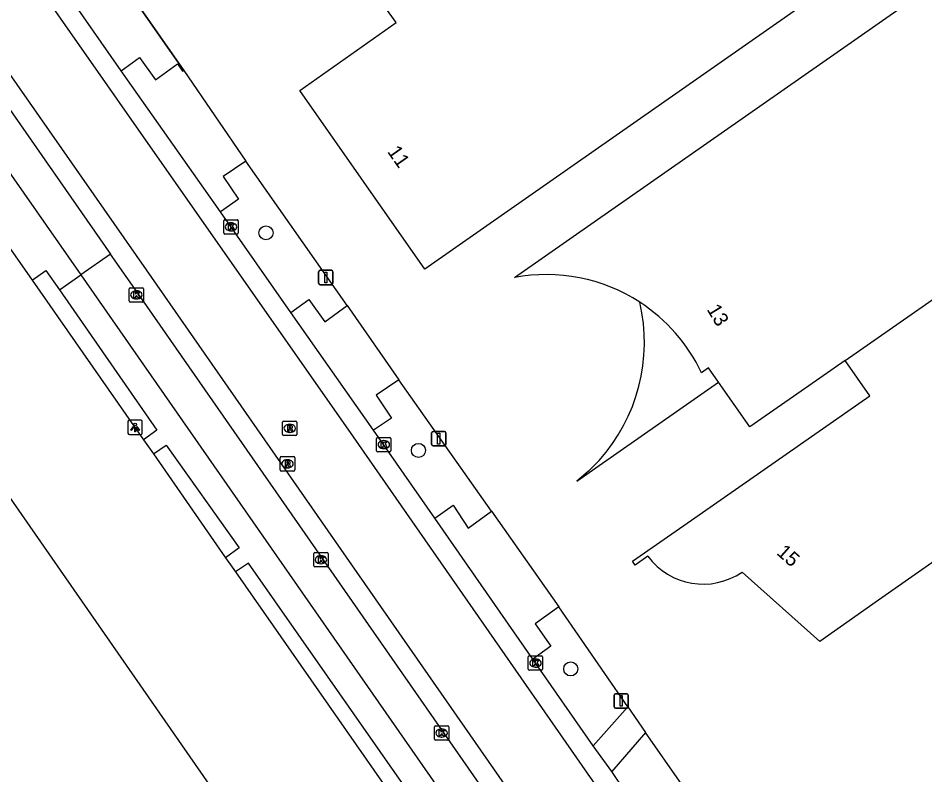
# Model space of a CAD drawing. Extents: x 156651 to 158072, y 387631 to 388990.
# Drawn here: x 157227.4 to 157290.6, y 388154.9 to 388207.5 of the extents above; entities that cross this region are included whole.
import ezdxf

# ---------------------------------------------------------------- set-up
doc = ezdxf.new("R2010")
doc.units = 0
for name, color, linetype in [('IMGEO_Berm_groen', 7, 'Continuous'), ('IMGEO_Boom', 7, 'Continuous'), ('IMGEO_Groenvoorziening', 7, 'Continuous'), ('IMGEO_Hek', 7, 'Continuous'), ('IMGEO_Kolk', 7, 'Continuous'), ('IMGEO_Lichtpunt', 7, 'Continuous'), ('IMGEO_Pand', 7, 'Continuous'), ('IMGEO_Pand_nummerreeks', 7, 'Continuous'), ('IMGEO_Pand_overbouw', 7, 'Continuous'), ('IMGEO_Rijbaan_lokaal_gesloten', 7, 'Continuous'), ('IMGEO_Rijbaan_lokaal_open', 7, 'Continuous'), ('IMGEO_Rioolput', 7, 'Continuous'), ('IMGEO_Verkeersbordpaal', 7, 'Continuous'), ('IMGEO_Voetpad_open', 7, 'Continuous')]:
    doc.layers.add(name, color=color, linetype=linetype)

msp = doc.modelspace()

# ---------------------------------------------------------------- linework, layer by layer
at = {"layer": 'IMGEO_Berm_groen'}
for points in [[(157238.976, 388203.904), (157232.439, 388213.235)], [(157250.344, 388187.533), (157243.285, 388197.598)], [(157260.401, 388173.229), (157253.951, 388182.374)], [(157269.88, 388159.622), (157265.086, 388166.567)], [(157273.661, 388154.215), (157271.116, 388157.832)]]:
    msp.add_lwpolyline(points, dxfattribs=at)
at = {"layer": 'IMGEO_Boom'}
for centre in [(157244.691, 388192.6), (157255.309, 388177.463), (157265.912, 388162.252)]:
    msp.add_circle(centre, 0.489, dxfattribs=at)
at = {"layer": 'IMGEO_Groenvoorziening'}
for points in [[(157228.416, 388189.316), (157236.169, 388178.201)], [(157236.847, 388177.226), (157241.87, 388169.99)], [(157242.574, 388169.007), (157265.86, 388135.653), (157271.06, 388128.215)]]:
    msp.add_lwpolyline(points, dxfattribs=at)
at = {"layer": 'IMGEO_Hek'}
msp.add_lwpolyline([(157232.439, 388213.235), (157238.976, 388203.904)], dxfattribs=at)
at = {"layer": 'IMGEO_Kolk'}
for p, q in [((157241.755, 388192.591), (157241.755, 388193.443)), ((157241.83, 388193.517), (157242.682, 388193.517)), ((157242.243, 388193.297), (157242.268, 388193.297)), ((157242.756, 388193.443), (157242.756, 388192.591)), ((157242.682, 388192.517), (157241.83, 388192.517)), ((157242.266, 388192.737), (157242.241, 388192.737)), ((157235.165, 388187.858), (157235.165, 388188.71)), ((157235.24, 388188.784), (157236.092, 388188.784)), ((157235.653, 388188.564), (157235.678, 388188.564)), ((157236.166, 388188.71), (157236.166, 388187.858)), ((157235.676, 388188.004), (157235.651, 388188.004)), ((157236.092, 388187.784), (157235.24, 388187.784)), ((157252.393, 388177.436), (157252.393, 388178.288)), ((157252.468, 388178.362), (157253.32, 388178.362)), ((157252.881, 388178.142), (157252.906, 388178.142)), ((157253.394, 388178.288), (157253.394, 388177.436)), ((157253.32, 388177.362), (157252.468, 388177.362)), ((157252.904, 388177.582), (157252.879, 388177.582)), ((157248.018, 388169.428), (157248.018, 388170.28)), ((157248.093, 388170.354), (157248.945, 388170.354)), ((157249.019, 388170.28), (157249.019, 388169.428)), ((157248.529, 388169.574), (157248.504, 388169.574)), ((157248.506, 388170.134), (157248.531, 388170.134)), ((157248.945, 388169.354), (157248.093, 388169.354)), ((157262.957, 388162.232), (157262.957, 388163.084)), ((157263.032, 388163.158), (157263.884, 388163.158)), ((157263.445, 388162.938), (157263.47, 388162.938)), ((157263.958, 388163.084), (157263.958, 388162.232)), ((157263.884, 388162.158), (157263.032, 388162.158)), ((157263.468, 388162.378), (157263.443, 388162.378)), ((157256.423, 388157.369), (157256.423, 388158.221)), ((157256.498, 388158.295), (157257.35, 388158.295)), ((157257.424, 388158.221), (157257.424, 388157.369)), ((157256.911, 388158.075), (157256.936, 388158.075)), ((157257.35, 388157.295), (157256.498, 388157.295)), ((157256.934, 388157.515), (157256.909, 388157.515))]:
    msp.add_line(p, q, dxfattribs=at)
for points in [[(157241.755, 388192.591), (157241.755, 388193.443)], [(157241.83, 388193.517), (157242.682, 388193.517)], [(157242.076, 388193.217), (157242.199, 388193.217), (157242.199, 388193.066), (157242.329, 388193.217), (157242.493, 388193.217), (157242.347, 388193.066), (157242.5, 388192.817), (157242.348, 388192.817), (157242.263, 388192.981), (157242.199, 388192.914), (157242.199, 388192.817), (157242.076, 388192.817), (157242.076, 388193.217)], [(157242.756, 388193.443), (157242.756, 388192.591)], [(157242.682, 388192.517), (157241.83, 388192.517)], [(157235.165, 388187.858), (157235.165, 388188.71)], [(157235.24, 388188.784), (157236.092, 388188.784)], [(157235.486, 388188.484), (157235.609, 388188.484), (157235.609, 388188.333), (157235.739, 388188.484), (157235.903, 388188.484), (157235.757, 388188.333), (157235.91, 388188.084), (157235.758, 388188.084), (157235.673, 388188.248), (157235.609, 388188.181), (157235.609, 388188.084), (157235.486, 388188.084), (157235.486, 388188.484)], [(157236.166, 388188.71), (157236.166, 388187.858)], [(157236.092, 388187.784), (157235.24, 388187.784)], [(157252.393, 388177.436), (157252.393, 388178.288)], [(157252.468, 388178.362), (157253.32, 388178.362)], [(157252.714, 388178.062), (157252.837, 388178.062), (157252.837, 388177.911), (157252.967, 388178.062), (157253.131, 388178.062), (157252.985, 388177.911), (157253.138, 388177.662), (157252.986, 388177.662), (157252.901, 388177.826), (157252.837, 388177.759), (157252.837, 388177.662), (157252.714, 388177.662), (157252.714, 388178.062)], [(157253.394, 388178.288), (157253.394, 388177.436)], [(157253.32, 388177.362), (157252.468, 388177.362)], [(157248.018, 388169.428), (157248.018, 388170.28)], [(157248.093, 388170.354), (157248.945, 388170.354)], [(157249.019, 388170.28), (157249.019, 388169.428)], [(157248.339, 388170.054), (157248.462, 388170.054), (157248.462, 388169.903), (157248.592, 388170.054), (157248.756, 388170.054), (157248.61, 388169.903), (157248.763, 388169.654), (157248.611, 388169.654), (157248.526, 388169.818), (157248.462, 388169.751), (157248.462, 388169.654), (157248.339, 388169.654), (157248.339, 388170.054)], [(157248.945, 388169.354), (157248.093, 388169.354)], [(157262.957, 388162.232), (157262.957, 388163.084)], [(157263.032, 388163.158), (157263.884, 388163.158)], [(157263.278, 388162.858), (157263.401, 388162.858), (157263.401, 388162.707), (157263.531, 388162.858), (157263.695, 388162.858), (157263.549, 388162.707), (157263.702, 388162.458), (157263.55, 388162.458), (157263.465, 388162.622), (157263.401, 388162.555), (157263.401, 388162.458), (157263.278, 388162.458), (157263.278, 388162.858)], [(157263.958, 388163.084), (157263.958, 388162.232)], [(157263.884, 388162.158), (157263.032, 388162.158)], [(157256.423, 388157.369), (157256.423, 388158.221)], [(157256.498, 388158.295), (157257.35, 388158.295)], [(157257.424, 388158.221), (157257.424, 388157.369)], [(157256.744, 388157.995), (157256.867, 388157.995), (157256.867, 388157.844), (157256.997, 388157.995), (157257.161, 388157.995), (157257.015, 388157.844), (157257.168, 388157.595), (157257.016, 388157.595), (157256.931, 388157.759), (157256.867, 388157.692), (157256.867, 388157.595), (157256.744, 388157.595), (157256.744, 388157.995)], [(157257.35, 388157.295), (157256.498, 388157.295)]]:
    msp.add_lwpolyline(points, dxfattribs=at)
for centre, start, end in [((157241.832, 388193.441), 91.55205, 178.44795), ((157241.832, 388193.441), 91.55205, 178.44795), ((157242.68, 388193.441), 1.55205, 88.44795), ((157242.68, 388193.441), 1.55205, 88.44795), ((157241.832, 388192.593), 181.55205, 268.44795), ((157241.832, 388192.593), 181.55205, 268.44795), ((157242.68, 388192.593), 271.55205, 358.44795), ((157242.68, 388192.593), 271.55205, 358.44795), ((157235.242, 388188.708), 91.55205, 178.44795), ((157235.242, 388188.708), 91.55205, 178.44795), ((157236.09, 388188.708), 1.55205, 88.44795), ((157236.09, 388188.708), 1.55205, 88.44795), ((157235.242, 388187.86), 181.55205, 268.44795), ((157235.242, 388187.86), 181.55205, 268.44795), ((157236.09, 388187.86), 271.55205, 358.44795), ((157236.09, 388187.86), 271.55205, 358.44795), ((157252.47, 388178.286), 91.55205, 178.44795), ((157252.47, 388178.286), 91.55205, 178.44795), ((157253.318, 388178.286), 1.55205, 88.44795), ((157253.318, 388178.286), 1.55205, 88.44795), ((157252.47, 388177.438), 181.55205, 268.44795), ((157252.47, 388177.438), 181.55205, 268.44795), ((157253.318, 388177.438), 271.55205, 358.44795), ((157253.318, 388177.438), 271.55205, 358.44795), ((157248.095, 388170.278), 91.55205, 178.44795), ((157248.095, 388170.278), 91.55205, 178.44795), ((157248.943, 388170.278), 1.55205, 88.44795), ((157248.943, 388170.278), 1.55205, 88.44795), ((157248.095, 388169.43), 181.55205, 268.44795), ((157248.095, 388169.43), 181.55205, 268.44795), ((157248.943, 388169.43), 271.55205, 358.44795), ((157248.943, 388169.43), 271.55205, 358.44795), ((157263.034, 388163.082), 91.55205, 178.44795), ((157263.034, 388163.082), 91.55205, 178.44795), ((157263.882, 388163.082), 1.55205, 88.44795), ((157263.882, 388163.082), 1.55205, 88.44795), ((157263.034, 388162.234), 181.55205, 268.44795), ((157263.034, 388162.234), 181.55205, 268.44795), ((157263.882, 388162.234), 271.55205, 358.44795), ((157263.882, 388162.234), 271.55205, 358.44795), ((157256.5, 388158.219), 91.55205, 178.44795), ((157256.5, 388158.219), 91.55205, 178.44795), ((157257.348, 388158.219), 1.55205, 88.44795), ((157257.348, 388158.219), 1.55205, 88.44795), ((157256.5, 388157.371), 181.55205, 268.44795), ((157256.5, 388157.371), 181.55205, 268.44795), ((157257.348, 388157.371), 271.55205, 358.44795), ((157257.348, 388157.371), 271.55205, 358.44795)]:
    msp.add_arc(centre, 0.0765, start, end, dxfattribs=at)
for centre, major_axis, ratio, start_param, end_param in [((157242.242, 388193.017), (-0.387, 0.002), 0.722429, 4.712389, 7.853982), ((157242.267, 388193.017), (-0.39, 0.002), 0.717154, 1.570796, 4.712389), ((157235.652, 388188.284), (-0.387, 0.002), 0.722429, 4.712389, 7.853982), ((157235.677, 388188.284), (-0.39, 0.002), 0.717154, 1.570796, 4.712389), ((157252.88, 388177.862), (-0.387, 0.002), 0.722429, 4.712389, 7.853982), ((157252.905, 388177.862), (-0.39, 0.002), 0.717154, 1.570796, 4.712389), ((157248.505, 388169.854), (-0.387, 0.002), 0.722429, 4.712389, 7.853982), ((157248.53, 388169.854), (-0.39, 0.002), 0.717154, 1.570796, 4.712389), ((157263.444, 388162.658), (-0.387, 0.002), 0.722429, 4.712389, 7.853982), ((157263.469, 388162.658), (-0.39, 0.002), 0.717154, 1.570796, 4.712389), ((157256.91, 388157.795), (-0.387, 0.002), 0.722429, 4.712389, 7.853982), ((157256.935, 388157.795), (-0.39, 0.002), 0.717154, 1.570796, 4.712389)]:
    msp.add_ellipse(centre, major_axis=major_axis, ratio=ratio, start_param=start_param, end_param=end_param, dxfattribs=at)
at = {"layer": 'IMGEO_Lichtpunt'}
for p, q in [((157235.081, 388179.468), (157235.081, 388178.661)), ((157235.081, 388179.468), (157235.081, 388178.661)), ((157235.983, 388179.563), (157235.175, 388179.563)), ((157235.983, 388179.563), (157235.175, 388179.563)), ((157236.077, 388178.661), (157236.077, 388179.468)), ((157236.077, 388178.661), (157236.077, 388179.468)), ((157235.175, 388178.567), (157235.983, 388178.567)), ((157235.175, 388178.567), (157235.983, 388178.567))]:
    msp.add_line(p, q, dxfattribs=at)
for points in [[(157235.455, 388179.132), (157235.494, 388179.104), (157235.306, 388178.842), (157235.268, 388178.869), (157235.455, 388179.132)], [(157235.557, 388179.084), (157235.604, 388179.084), (157235.604, 388178.762), (157235.557, 388178.762), (157235.557, 388179.084)], [(157235.667, 388179.104), (157235.705, 388179.131), (157235.892, 388178.869), (157235.853, 388178.841), (157235.667, 388179.104)]]:
    msp.add_lwpolyline(points, dxfattribs=at)
msp.add_circle((157235.58, 388179.266), 0.0994, dxfattribs=at)
for centre, start, end in [((157235.175, 388179.468), 90, 180), ((157235.175, 388179.468), 90, 180), ((157235.983, 388179.468), 0, 90), ((157235.983, 388179.468), 0, 90), ((157235.175, 388178.661), 180, 270), ((157235.175, 388178.661), 180, 270), ((157235.983, 388178.661), 270, 0), ((157235.983, 388178.661), 270, 360)]:
    msp.add_arc(centre, 0.0946, start, end, dxfattribs=at)
at = {"layer": 'IMGEO_Pand'}
for points in [[(157288.942, 388238.83), (157300.956, 388221.652), (157259.851, 388192.936), (157255.752, 388190.072), (157247.043, 388202.516), (157253.751, 388207.231), (157250.416, 388211.885), (157254.514, 388214.751), (157273.145, 388227.807)], [(157261.992, 388189.493), (157266.09, 388192.357), (157305.779, 388220.064), (157307.103, 388218.166), (157309.496, 388219.835), (157317.678, 388208.106), (157315.286, 388206.437), (157316.061, 388205.325), (157295.222, 388190.815)], [(157295.222, 388190.815), (157296.945, 388188.34), (157306.793, 388195.191), (157315.806, 388182.235), (157299.201, 388170.684), (157297.021, 388173.804), (157287.352, 388167.038), (157283.255, 388164.171), (157277.844, 388168.992)], [(157285.036, 388183.723), (157295.222, 388190.815)], [(157271.289, 388170.091), (157270.399, 388169.476), (157270.213, 388169.744), (157274.318, 388172.6), (157286.756, 388181.252), (157285.036, 388183.723)], [(157285.036, 388183.723), (157282.491, 388181.951), (157278.39, 388179.09), (157276.216, 388182.206), (157275.518, 388183.206), (157275.025, 388182.861)], [(157257.578, 388129.897), (157248.5, 388123.588), (157239.125, 388137.125), (157237.62, 388139.301), (157246.706, 388145.644), (157221.693, 388181.584), (157212.642, 388175.281), (157211.076, 388177.53), (157208.169, 388175.506), (157161.84, 388143.245), (157189.962, 388102.891), (157199.722, 388088.956), (157214.226, 388068.097), (157272.425, 388108.581), (157257.578, 388129.897)]]:
    msp.add_lwpolyline(points, dxfattribs=at)
for centre, radius, start, end in [((157264.215, 388177.734), 11.967, 57.02063, 100.70526), ((157264.213, 388177.74), 11.964, 25.34614, 56.99928), ((157275.137, 388172.942), 4.789, 216.53451, 304.43031)]:
    msp.add_arc(centre, radius, start, end, dxfattribs=at)
at = {"layer": 'IMGEO_Pand_overbouw'}
msp.add_lwpolyline([(157267.89, 388176.764), (157267.153, 388176.012), (157266.338, 388175.314), (157267.905, 388176.407), (157276.216, 388182.206), (157275.518, 388183.206), (157275.025, 388182.861)], dxfattribs=at)
for centre, radius, start, end in [((157258.767, 388184.987), 12.282, 317.96841, 13.11083), ((157264.213, 388177.74), 11.964, 25.34614, 56.99928)]:
    msp.add_arc(centre, radius, start, end, dxfattribs=at)
at = {"layer": 'IMGEO_Rijbaan_lokaal_gesloten'}
for points in [[(157341.899, 388076.038), (157340.456, 388076.982), (157309.901, 388101.717), (157302.391, 388108.413), (157297.417, 388113.326), (157292.839, 388118.359), (157292.715, 388118.524), (157290.068, 388122.059), (157284.128, 388130.537), (157250.785, 388178.4), (157218.017, 388225.194), (157168.536, 388296.106), (157166.328, 388299.54), (157165.346, 388302.72), (157165.232, 388304.849), (157165.572, 388307.171), (157166.44, 388309.461), (157166.862, 388310.136)], [(157159.256, 388297.816), (157160.307, 388298.772), (157166.301, 388290.299), (157236.347, 388190.018), (157288.771, 388114.767), (157287.657, 388113.917)], [(157234.617, 388203.884), (157230.6, 388209.644)], [(157241.532, 388194.055), (157234.617, 388203.884)], [(157225.926, 388202.493), (157233.871, 388191.118)], [(157246.429, 388187.061), (157241.532, 388194.055)], [(157274.579, 388132.691), (157236.036, 388188.018), (157233.871, 388191.118)], [(157252.169, 388178.864), (157246.429, 388187.061)], [(157256.455, 388172.746), (157252.169, 388178.864)], [(157263.265, 388162.929), (157256.455, 388172.746)], [(157267.467, 388156.891), (157263.265, 388162.929)], [(157268.767, 388155.125), (157267.467, 388156.891)], [(157269.683, 388153.769), (157268.767, 388155.125)]]:
    msp.add_lwpolyline(points, dxfattribs=at)
at = {"layer": 'IMGEO_Rijbaan_lokaal_open'}
for points in [[(157234.617, 388203.884), (157235.884, 388204.792), (157236.993, 388203.247), (157238.529, 388204.367), (157238.878, 388203.847), (157238.976, 388203.904)], [(157238.976, 388203.904), (157243.285, 388197.598)], [(157243.285, 388197.598), (157241.71, 388196.51), (157242.786, 388194.938), (157241.532, 388194.055)], [(157246.429, 388187.061), (157247.671, 388187.969), (157248.791, 388186.418), (157250.344, 388187.533)], [(157250.344, 388187.533), (157253.951, 388182.374)], [(157253.951, 388182.374), (157252.369, 388181.296), (157253.443, 388179.711), (157252.169, 388178.864)], [(157256.455, 388172.746), (157257.73, 388173.658), (157258.77, 388172.059), (157260.401, 388173.229)], [(157260.401, 388173.229), (157265.086, 388166.567)], [(157265.086, 388166.567), (157263.445, 388165.387), (157264.54, 388163.836), (157263.265, 388162.929)]]:
    msp.add_lwpolyline(points, dxfattribs=at)
at = {"layer": 'IMGEO_Rioolput'}
for p, q in [((157245.845, 388178.571), (157245.845, 388179.423)), ((157245.92, 388179.497), (157246.772, 388179.497)), ((157246.333, 388179.277), (157246.358, 388179.277)), ((157246.846, 388179.423), (157246.846, 388178.571)), ((157246.772, 388178.497), (157245.92, 388178.497)), ((157246.356, 388178.717), (157246.331, 388178.717)), ((157245.689, 388176.101), (157245.689, 388176.953)), ((157245.764, 388177.027), (157246.616, 388177.027)), ((157246.177, 388176.807), (157246.202, 388176.807)), ((157246.69, 388176.953), (157246.69, 388176.101)), ((157246.616, 388176.027), (157245.764, 388176.027)), ((157246.2, 388176.247), (157246.175, 388176.247))]:
    msp.add_line(p, q, dxfattribs=at)
for points in [[(157245.845, 388178.571), (157245.845, 388179.423)], [(157245.92, 388179.497), (157246.772, 388179.497)], [(157246.434, 388179.195), (157246.182, 388179.197), (157246.182, 388178.797)], [(157246.36, 388179.116), (157246.306, 388179.116), (157246.306, 388179.035)], [(157246.306, 388179.035), (157246.358, 388179.035)], [(157246.846, 388179.423), (157246.846, 388178.571)], [(157246.772, 388178.497), (157245.92, 388178.497)], [(157246.182, 388178.797), (157246.306, 388178.797), (157246.306, 388178.959), (157246.317, 388178.959)], [(157246.364, 388178.93), (157246.435, 388178.797), (157246.575, 388178.797), (157246.51, 388178.923)], [(157245.689, 388176.101), (157245.689, 388176.953)], [(157245.764, 388177.027), (157246.616, 388177.027)], [(157246.278, 388176.725), (157246.026, 388176.727), (157246.026, 388176.327)], [(157246.026, 388176.327), (157246.15, 388176.327), (157246.15, 388176.489), (157246.161, 388176.489)], [(157246.204, 388176.646), (157246.15, 388176.646), (157246.15, 388176.565)], [(157246.15, 388176.565), (157246.202, 388176.565)], [(157246.69, 388176.953), (157246.69, 388176.101)], [(157246.616, 388176.027), (157245.764, 388176.027)], [(157246.208, 388176.46), (157246.279, 388176.327), (157246.419, 388176.327), (157246.354, 388176.453)]]:
    msp.add_lwpolyline(points, dxfattribs=at)
for centre, radius, start, end in [((157245.922, 388179.421), 0.0765, 91.55205, 178.44795), ((157245.922, 388179.421), 0.0765, 91.55205, 178.44795), ((157246.342, 388179.224), 0.19, 274.7715, 282.96867), ((157246.366, 388179.02), 0.0964, 77.00612, 93.18647), ((157246.38, 388179.077), 0.0378, 276.66336, 79.67722), ((157246.433, 388179.085), 0.109, 350.36119, 89.41601), ((157246.431, 388179.085), 0.112, 277.58423, 350.98172), ((157246.77, 388179.421), 0.0765, 1.55205, 88.44795), ((157246.77, 388179.421), 0.0765, 1.55205, 88.44795), ((157245.922, 388178.573), 0.0765, 181.55205, 268.44795), ((157245.922, 388178.573), 0.0765, 181.55205, 268.44795), ((157246.316, 388178.906), 0.0533, 26.02933, 88.69889), ((157246.415, 388178.87), 0.108, 29.51342, 73.79051), ((157246.77, 388178.573), 0.0765, 271.55205, 358.44795), ((157246.77, 388178.573), 0.0765, 271.55205, 358.44795), ((157245.766, 388176.951), 0.0765, 91.55205, 178.44795), ((157245.766, 388176.951), 0.0765, 91.55205, 178.44795), ((157246.16, 388176.436), 0.0533, 26.02933, 88.69889), ((157246.186, 388176.754), 0.19, 274.7715, 282.96867), ((157246.21, 388176.55), 0.0964, 77.00612, 93.18647), ((157246.224, 388176.607), 0.0378, 276.66336, 79.67722), ((157246.277, 388176.615), 0.109, 350.36119, 89.41601), ((157246.275, 388176.615), 0.112, 277.58423, 350.98172), ((157246.259, 388176.4), 0.108, 29.51342, 73.79051), ((157246.614, 388176.951), 0.0765, 1.55205, 88.44795), ((157246.614, 388176.951), 0.0765, 1.55205, 88.44795), ((157245.766, 388176.103), 0.0765, 181.55205, 268.44795), ((157245.766, 388176.103), 0.0765, 181.55205, 268.44795), ((157246.614, 388176.103), 0.0765, 271.55205, 358.44795), ((157246.614, 388176.103), 0.0765, 271.55205, 358.44795)]:
    msp.add_arc(centre, radius, start, end, dxfattribs=at)
for centre, major_axis, ratio, start_param, end_param in [((157246.332, 388178.997), (-0.387, 0.002), 0.722429, 4.712389, 7.853982), ((157246.357, 388178.997), (-0.39, 0.002), 0.717154, 1.570796, 4.712389), ((157246.176, 388176.527), (-0.387, 0.002), 0.722429, 4.712389, 7.853982), ((157246.201, 388176.527), (-0.39, 0.002), 0.717154, 1.570796, 4.712389)]:
    msp.add_ellipse(centre, major_axis=major_axis, ratio=ratio, start_param=start_param, end_param=end_param, dxfattribs=at)
at = {"layer": 'IMGEO_Verkeersbordpaal'}
for p, q in [((157248.359, 388189.093), (157248.359, 388189.893)), ((157248.359, 388189.893), (157248.359, 388189.093)), ((157248.459, 388189.993), (157249.249, 388189.993)), ((157249.249, 388189.993), (157248.459, 388189.993)), ((157249.349, 388189.893), (157249.349, 388189.093)), ((157249.349, 388189.093), (157249.349, 388189.893)), ((157249.249, 388188.993), (157248.459, 388188.993)), ((157248.459, 388188.993), (157249.249, 388188.993)), ((157256.227, 388177.877), (157256.227, 388178.677)), ((157256.227, 388178.677), (157256.227, 388177.877)), ((157256.327, 388178.777), (157257.117, 388178.777)), ((157257.117, 388178.777), (157256.327, 388178.777)), ((157257.217, 388178.677), (157257.217, 388177.877)), ((157257.217, 388177.877), (157257.217, 388178.677)), ((157257.117, 388177.777), (157256.327, 388177.777)), ((157256.327, 388177.777), (157257.117, 388177.777)), ((157268.93, 388159.627), (157268.93, 388160.427)), ((157268.93, 388160.427), (157268.93, 388159.627)), ((157269.03, 388160.527), (157269.82, 388160.527)), ((157269.82, 388160.527), (157269.03, 388160.527)), ((157269.92, 388160.427), (157269.92, 388159.627)), ((157269.92, 388159.627), (157269.92, 388160.427)), ((157269.82, 388159.527), (157269.03, 388159.527)), ((157269.03, 388159.527), (157269.82, 388159.527))]:
    msp.add_line(p, q, dxfattribs=at)
for points in [[(157248.779, 388189.868), (157248.929, 388189.868), (157248.929, 388189.118), (157248.779, 388189.118), (157248.779, 388189.868)], [(157256.647, 388178.652), (157256.797, 388178.652), (157256.797, 388177.902), (157256.647, 388177.902), (157256.647, 388178.652)], [(157269.35, 388160.402), (157269.5, 388160.402), (157269.5, 388159.652), (157269.35, 388159.652), (157269.35, 388160.402)]]:
    msp.add_lwpolyline(points, dxfattribs=at)
for centre, start, end in [((157248.459, 388189.893), 90, 180), ((157248.459, 388189.893), 90, 180), ((157249.249, 388189.893), 0, 90), ((157249.249, 388189.893), 360, 90), ((157248.459, 388189.093), 180, 270), ((157248.459, 388189.093), 180, 270), ((157249.249, 388189.093), 270, 0), ((157249.249, 388189.093), 270, 0), ((157256.327, 388178.677), 90, 180), ((157256.327, 388178.677), 90, 180), ((157257.117, 388178.677), 0, 90), ((157257.117, 388178.677), 360, 90), ((157256.327, 388177.877), 180, 270), ((157256.327, 388177.877), 180, 270), ((157257.117, 388177.877), 270, 0), ((157257.117, 388177.877), 270, 0), ((157269.03, 388160.427), 90, 180), ((157269.03, 388160.427), 90, 180), ((157269.82, 388160.427), 0, 90), ((157269.82, 388160.427), 360, 90), ((157269.03, 388159.627), 180, 270), ((157269.03, 388159.627), 180, 270), ((157269.82, 388159.627), 270, 0), ((157269.82, 388159.627), 270, 0)]:
    msp.add_arc(centre, 0.1, start, end, dxfattribs=at)
at = {"layer": 'IMGEO_Voetpad_open'}
for points in [[(157223.842, 388201.037), (157231.797, 388189.67)], [(157222.314, 388197.962), (157228.416, 388189.316)], [(157233.871, 388191.118), (157231.797, 388189.67)], [(157228.416, 388189.316), (157229.362, 388189.981), (157230.32, 388188.624)], [(157230.32, 388188.624), (157231.797, 388189.67)], [(157231.797, 388189.67), (157272.471, 388131.321)], [(157230.32, 388188.624), (157237.097, 388178.88), (157236.169, 388178.201)], [(157236.169, 388178.201), (157236.847, 388177.226)], [(157236.847, 388177.226), (157237.731, 388177.828), (157242.83, 388170.675), (157241.87, 388169.99)], [(157241.87, 388169.99), (157242.574, 388169.007)], [(157270.989, 388130.287), (157243.463, 388169.622), (157242.574, 388169.007)], [(157267.467, 388156.891), (157269.88, 388159.622)], [(157269.88, 388159.622), (157271.116, 388157.832)], [(157271.116, 388157.832), (157268.767, 388155.125)]]:
    msp.add_lwpolyline(points, dxfattribs=at)

# ---------------------------------------------------------------- texts
at = {"layer": 'IMGEO_Pand_nummerreeks'}
for s, rotation, p in [('11', 304.98646, (157253.106, 388198.248)), ('13', 301.17442, (157275.36, 388187.274)), ('15', 318.30013, (157280.195, 388170.272))]:
    msp.add_text(s, height=1, rotation=rotation, dxfattribs=at).set_placement(p)

doc.saveas('drawing.dxf')
